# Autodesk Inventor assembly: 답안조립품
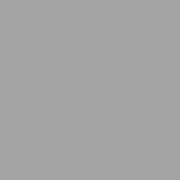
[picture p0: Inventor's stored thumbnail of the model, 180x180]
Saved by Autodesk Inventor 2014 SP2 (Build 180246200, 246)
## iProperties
Created: 2019-01
Part Number: 답안조립품
Document SubType Name: Assembly
Designer: CM-CAD
Author: CM-CAD
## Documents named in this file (1)
- C:\Users\cm\Desktop\490107V1025\답안조립품.iam
